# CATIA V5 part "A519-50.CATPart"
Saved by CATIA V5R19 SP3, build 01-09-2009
Part number: A519-50
Bounding box of the stored display mesh (mm): x -24.993 to 24.993, y -24.918 to 24.918, z 0 to 70
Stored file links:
  C:\Users\d.catalano\Desktop\CATALOGO CAD\04 MOLLE\A519\A519-50.CATPart
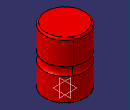
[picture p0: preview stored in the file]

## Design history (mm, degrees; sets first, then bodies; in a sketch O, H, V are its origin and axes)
Body1 "A519-50" (main body)
  Sketch1 on yz-plane, origin (0, 0, 0), H (0, 1, 0), V (0, 0, 1)
    line L1 (0, 0) -> (23, 0)
    line L2 (25, 2) -> (25, 29.9049)
    line L3 (23, 70) -> (0, 70)
    line L4 (0, 70) -> (0, 0)
    construction line L5 (-5.6038, 35) -> (28.5463, 35)
    arc A1 centre (29.8, 35) radius 7 from (25, 40.0951) to (25, 29.9049) ccw
    point P2 (29.8, 35)
    construction line L6 (22.8, 49.6338) -> (22.8, -12.4196)
    line L7 (25, 40.0951) -> (25, 68)
    arc A2 centre (23, 68) radius 2 from (23, 70) to (25, 68) cw
    arc A3 centre (23, 2) radius 2 from (23, 0) to (25, 2) ccw
    distance L4 L2 = 25
    distance L1 L3 = 70
    distance L5 L3 = 35
    radius A1 = 7
    distance L2 L6 = 2.2
    radius A2 = 2
    radius A3 = 2
    horizontal: L1 H, L3 H, L5 H
    vertical: L2 V, L4 V, L6 V, L7 V
    coincidence: P2 L5, L2 L7
    tangency: A1 L6, A2 L3, A2 L7, A3 L1, A3 L2
  Shaft1 "Albero": profile Sketch1, axis Sketch1.L4, angle 360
